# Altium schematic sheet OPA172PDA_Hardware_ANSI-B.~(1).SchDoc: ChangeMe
size 431 x 279 mm; Date: Not shown in title block; ApprovedBy: Not shown in title block; CheckedBy: Not shown in title block; Author: Not shown in title block; CompanyName: Not shown in title block; DrawnBy: Enter Full Name; Engineer: Not shown in title block; Organization: Not shown in title block; Address1: Not shown in title block; Address2: Not shown in title block; Address3: Not shown in title block; Address4: Not shown in title block; DocumentNumber: 3; Revision: Use project parameter SCH_Rev; SheetNumber: 3; SheetTotal: 3; PageSetup: Record=PageOptions|CenterHorizontal=True|CenterVertical=True|PrintScale=1.00|XCorrection=1.00|YCorrection=1.00|PrintKind=0|BorderSize=5000000|LeftOffset=0|BottomOffset=0|Orientation=2|PaperLength=1000|PaperWidth=1000|Scale=100|PaperSource=15|PrintQuality=600|MediaType=1|DitherType=10|PaperKind=Letter|PrintScaleMode=1
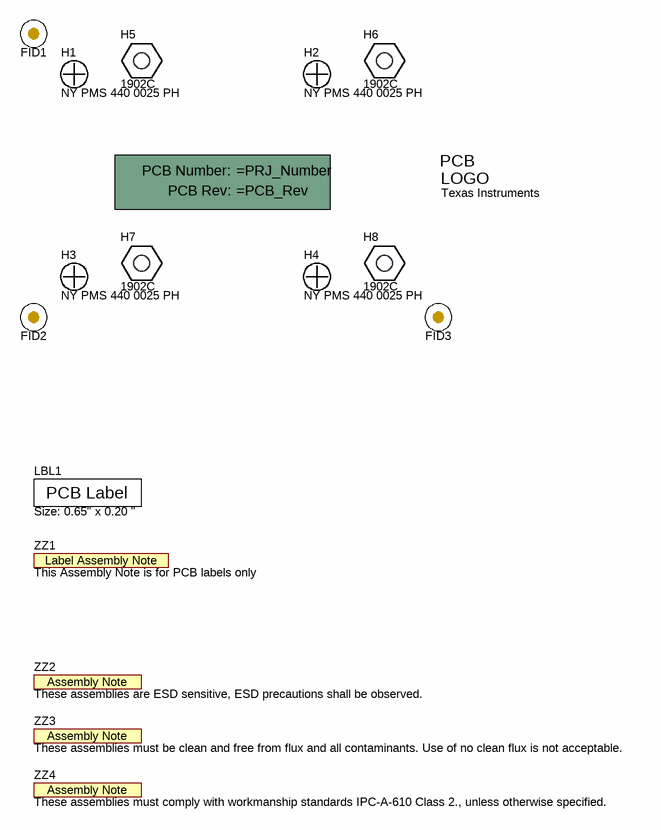
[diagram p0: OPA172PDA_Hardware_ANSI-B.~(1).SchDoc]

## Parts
!PCB  Printed Circuit Board  (value not drawn)  (mechanical)
FID1  Fiducial  [Fiducial10-20]  (value not drawn)
FID2  Fiducial  [Fiducial10-20]  (value not drawn)
FID3  Fiducial  [Fiducial10-20]  (value not drawn)
H1  NY PMS 440 0025 PH  [NY PMS 440 0025 PH]
H2  NY PMS 440 0025 PH  [NY PMS 440 0025 PH]
H3  NY PMS 440 0025 PH  [NY PMS 440 0025 PH]
H4  NY PMS 440 0025 PH  [NY PMS 440 0025 PH]
H5  1902C  [Keystone_1902C]
H6  1902C  [Keystone_1902C]
H7  1902C  [Keystone_1902C]
H8  1902C  [Keystone_1902C]
LBL1  Size: 0.65" x 0.20 "  [Label_650x200]
Logo1  Texas Instruments  [TI_Stacked_SolderMask_Small]  (no BOM)
ZZ1  This Assembly Note is for PCB labels only  [AssemblyNoteLabel]  (no BOM)
ZZ2  These assemblies are ESD sensitive, ESD precautions shall be observed.  [AssemblyNote]  (no BOM)
ZZ3  These assemblies must be clean and free from flux and all contaminants. Use of no clean flux is not acceptable.  [AssemblyNote]  (no BOM)
ZZ4  These assemblies must comply with workmanship standards IPC-A-610 Class 2., unless otherwise specified.  [AssemblyNote]  (no BOM)

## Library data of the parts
!PCB = PCB: Manufacturer: Any; SymbolCreator: a0412235
FID1-FID3 = Fiducial: Fiducial mark.  There is nothing to buy or mount.; SymbolCreator: codlsc
H1-H4 = NY PMS 440 0025 PH: Machine Screw, Round, #4-40 x 1/4, Nylon, Philips panhead; Manufacturer: B&F Fastener Supply; CompType: Hardware; SymbolCreator: codlsc; U/M: EA
H5-H8 = 1902C: Standoff, Hex, 0.5"L #4-40 Nylon; Manufacturer: Keystone; CompType: Hardware
LBL1 = THT-14-423-10: Thermal Transfer Printable Labels, 0.650" W x 0.200" H - 10,000 per roll; Manufacturer: Brady; SymbolCreator: a0412235; CompType: Label
Logo1 = TI_Logo: Texas Instrument Corporate Signature; SymbolCreator: codlsc
ZZ1 = AssemblyNoteLabel: SymbolCreator: a0412235
ZZ2-ZZ4 = AssemblyNote: SymbolCreator: codlsc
